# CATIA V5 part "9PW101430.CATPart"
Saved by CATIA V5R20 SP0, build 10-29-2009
Part number: 9PW101430
Revision: ANY
Definition: UNKNOWN
Nomenclature: 9PW101430
Source: Unknown
Bounding box of the stored display mesh (mm): x -174.496 to 0, y -14.062 to 5, z -7.1 to 7.1
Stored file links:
  C:\Users\Utente\Desktop\IO LAVORO\3D X SITO CF\CUMSA\3D files PW\pw101430\pw101430_ejection\9PW101430.CATPart
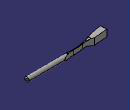
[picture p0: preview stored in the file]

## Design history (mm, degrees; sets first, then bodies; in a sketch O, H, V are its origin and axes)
Body1 "Chaflán4" (main body)
  Solid1: solid without history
